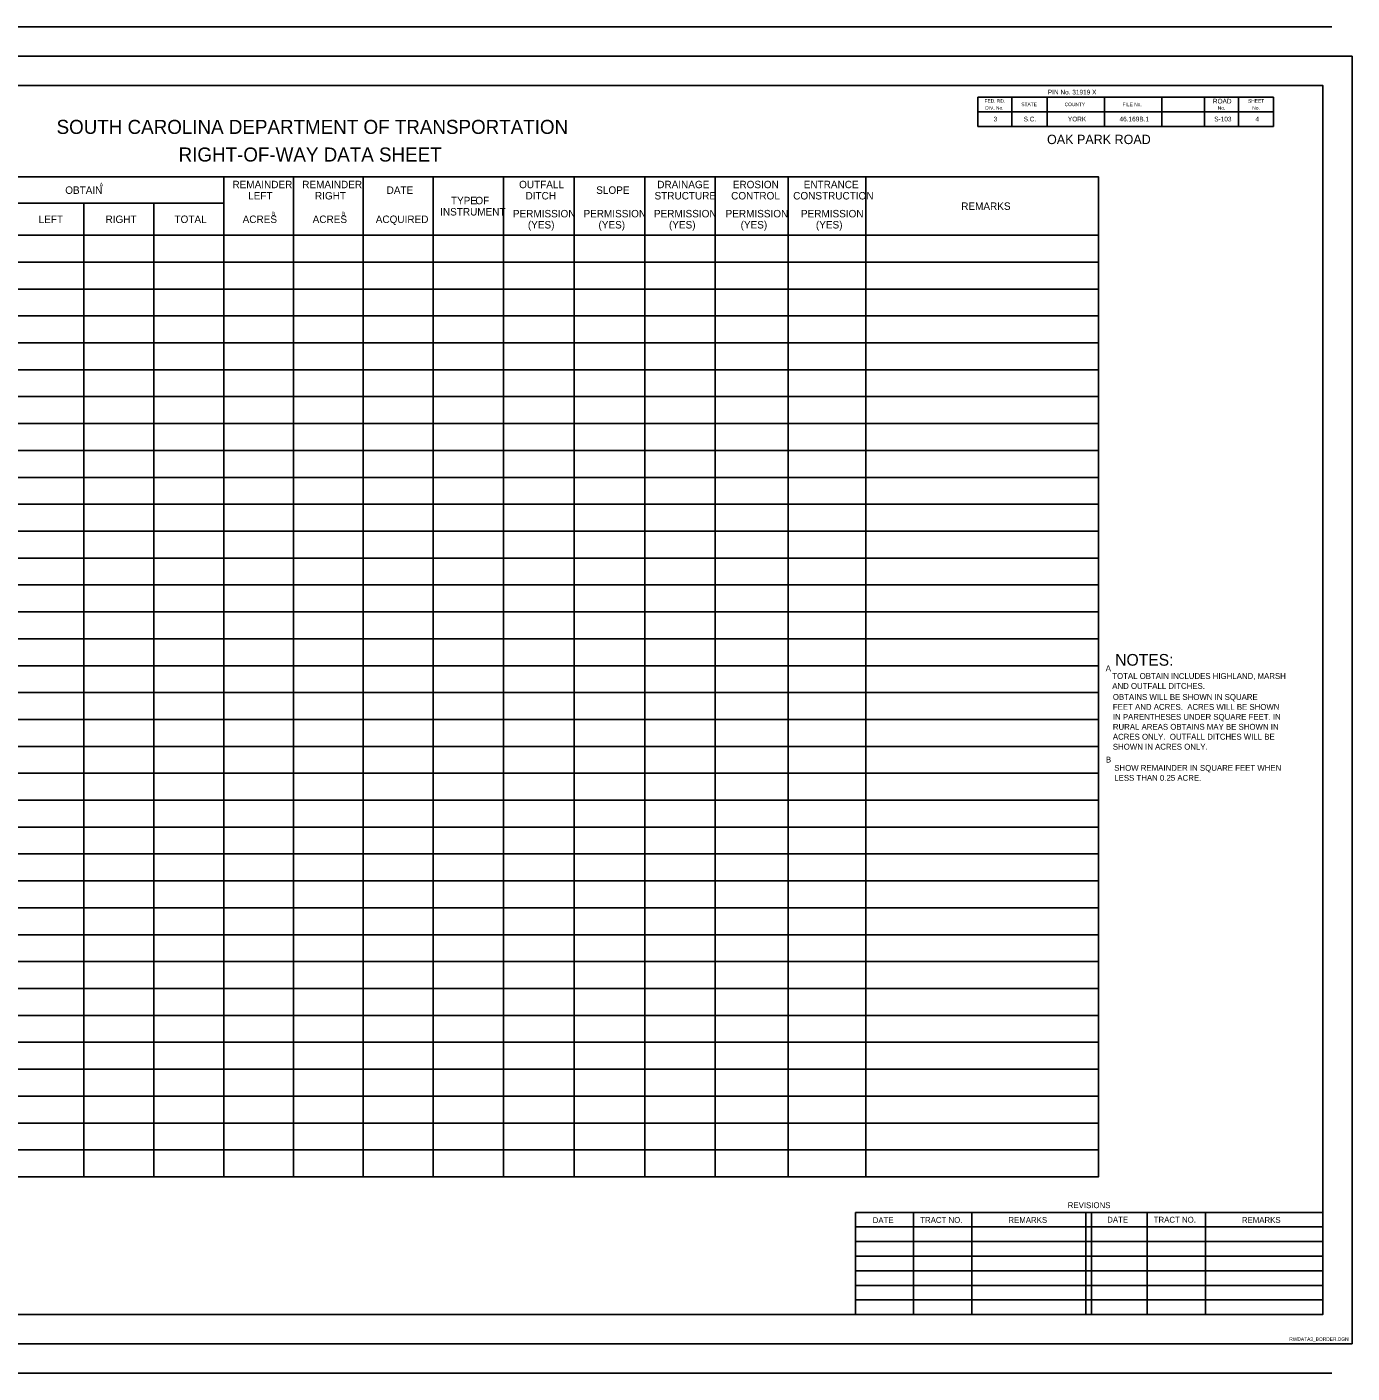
# Model space of a CAD drawing. Extents: x -19 to 1777, y -25 to 1125.
# Drawn here: x 646 to 1777, y -25 to 1125 of the extents above; entities that cross this region are included whole.
import ezdxf

# ---------------------------------------------------------------- set-up
doc = ezdxf.new("R2010")
doc.units = 0
for name, color, linetype in [('RD_SHT_Bndy', 7, 'Continuous'), ('RD_SHT_Iplotshp', 7, 'Continuous'), ('RD_SHT_MjGrid', 7, 'Continuous'), ('RD_SHT_TX', 7, 'Continuous'), ('RD_TX_RW', 7, 'Continuous')]:
    doc.layers.add(name, color=color, linetype=linetype)

msp = doc.modelspace()

# ---------------------------------------------------------------- linework, layer by layer
at = {"layer": 'RD_SHT_Bndy'}
for p, q in [((0, 1125), (1760, 1125)), ((0, 1100), (1760, 1100)), ((1457.9, 1065), (1710.4, 1065)), ((1457.9, 1065), (1457.9, 1052.5)), ((1486.9, 1065), (1486.9, 1052.5)), ((1516.9, 1065), (1516.9, 1052.5)), ((1565.9, 1065), (1565.9, 1052.5)), ((1614.9, 1065), (1614.9, 1052.5)), ((1651.4, 1065), (1651.4, 1052.5)), ((1680.4, 1065), (1680.4, 1052.5)), ((1710.4, 1065), (1710.4, 1052.5)), ((1457.9, 1052.5), (1710.4, 1052.5)), ((1457.9, 1052.5), (1457.9, 1040)), ((1486.9, 1052.5), (1486.9, 1049.4)), ((1486.9, 1049.4), (1486.9, 1040)), ((1516.9, 1052.5), (1516.9, 1040)), ((1565.9, 1052.5), (1565.9, 1040)), ((1614.9, 1052.5), (1614.9, 1040)), ((1651.4, 1052.5), (1651.4, 1040)), ((1680.4, 1052.5), (1680.4, 1040)), ((1710.4, 1052.5), (1710.4, 1040)), ((1457.9, 1040), (1710.4, 1040)), ((1353.4, 112.2), (1752.4, 112.2)), ((1353.4, 112.2), (1353.4, 25)), ((1402.9, 112.2), (1402.9, 25)), ((1452.7, 112.2), (1452.7, 25)), ((1549.9, 112.2), (1549.9, 25)), ((1554.9, 112.2), (1554.9, 25)), ((1602.3, 112.2), (1602.3, 25)), ((1652.1, 112.2), (1652.1, 25)), ((1353.4, 99.8), (1752.4, 99.8)), ((1353.4, 87.3), (1752.4, 87.3)), ((1353.4, 74.9), (1752.4, 74.9)), ((1353.4, 62.4), (1752.4, 62.4)), ((1353.4, 49.9), (1752.4, 49.9)), ((1353.4, 37.5), (1752.4, 37.5)), ((0, 0), (1760, 0)), ((0, -25), (1760, -25))]:
    msp.add_line(p, q, dxfattribs=at)
for points in [[(77.4, 1075), (1752.4, 1075), (1752.4, 25), (77.4, 25)], [(218, 142.7), (1560.9, 142.7), (1560.9, 996.8), (218, 996.8)]]:
    msp.add_lwpolyline(points, close=True, dxfattribs=at)
at = {"layer": 'RD_SHT_Iplotshp'}
msp.add_lwpolyline([(-18.6, 1100), (1777.4, 1100), (1777.4, 0), (-18.6, 0)], close=True, dxfattribs=at)
at = {"layer": 'RD_SHT_MjGrid'}
for p, q in [((218, 996.8), (1560.9, 996.8)), ((813.7, 142.7), (813.7, 996.8)), ((873.3, 142.7), (873.3, 996.8)), ((932.9, 142.7), (932.9, 996.8)), ((992.6, 142.7), (992.6, 996.8)), ((1052.8, 142.7), (1052.8, 996.8)), ((1113.1, 142.7), (1113.1, 996.8)), ((1173.3, 142.7), (1173.3, 996.8)), ((1233.6, 142.7), (1233.6, 996.8)), ((1295.7, 142.7), (1295.7, 996.8)), ((1362.1, 142.7), (1362.1, 996.8)), ((1560.9, 142.7), (1560.9, 996.8)), ((575.2, 974.4), (813.7, 974.4)), ((694.4, 142.7), (694.4, 974.4)), ((754, 142.7), (754, 974.4)), ((218, 947.1), (1560.9, 947.1)), ((992.6, 947.1), (1362.1, 947.1)), ((1362.1, 947.1), (1560.9, 947.1)), ((218, 924.1), (1560.9, 924.1)), ((218, 901.1), (1560.9, 901.1)), ((218, 878.1), (1560.9, 878.1)), ((218, 855.1), (1560.9, 855.1)), ((218, 832.1), (1560.9, 832.1)), ((218, 809.2), (1560.9, 809.2)), ((218, 786.2), (1560.9, 786.2)), ((218, 763.2), (1560.9, 763.2)), ((218, 740.2), (1560.9, 740.2)), ((218, 717.2), (1560.9, 717.2)), ((218, 694.3), (1560.9, 694.3)), ((218, 671.3), (1560.9, 671.3)), ((218, 648.3), (1560.9, 648.3)), ((218, 625.3), (1560.9, 625.3)), ((218, 602.3), (1560.9, 602.3)), ((218, 579.3), (1560.9, 579.3)), ((218, 556.4), (1560.9, 556.4)), ((218, 533.4), (1560.9, 533.4)), ((218, 510.4), (1560.9, 510.4)), ((218, 487.4), (1560.9, 487.4)), ((218, 464.4), (1560.9, 464.4)), ((218, 441.4), (1560.9, 441.4)), ((218, 418.5), (1560.9, 418.5)), ((218, 395.5), (1560.9, 395.5)), ((218, 372.5), (1560.9, 372.5)), ((218, 349.5), (1560.9, 349.5)), ((218, 326.5), (1560.9, 326.5)), ((218, 303.6), (1560.9, 303.6)), ((218, 280.6), (1560.9, 280.6)), ((218, 257.6), (1560.9, 257.6)), ((218, 234.6), (1560.9, 234.6)), ((218, 211.6), (1560.9, 211.6)), ((218, 188.6), (1560.9, 188.6)), ((218, 165.7), (1560.9, 165.7)), ((218, 142.7), (1560.9, 142.7))]:
    msp.add_line(p, q, dxfattribs=at)

# ---------------------------------------------------------------- texts
at = {"layer": 'RD_SHT_TX'}
for s, height, p in [('PIN No. 31919 X   ', 4, (1517.6, 1067.3)), ('FED. RD.', 3, (1463.5, 1060.3)), ('STATE', 3, (1494.9, 1057.3)), ('COUNTY', 3, (1531.9, 1057.3)), ('FILE No.', 3, (1581.4, 1057.3)), ('      ROAD      ', 4, (1649.3, 1059.6)), ('SHEET', 3, (1688.5, 1060.3)), ('DIV. No.', 3, (1464.1, 1054.3)), ('3', 4, (1471.2, 1044.3)), ('S.C.', 4, (1496.9, 1044.3)), ('      YORK      ', 4, (1525.5, 1044.3)), ('   46.169B.1    ', 4, (1574.2, 1044.3)), ('     S-103      ', 4, (1652, 1044.3)), ('No.', 3, (1662.7, 1054.3)), ('No.', 3, (1692.2, 1054.3)), ('       4        ', 4, (1684.1, 1044.3)), ('SOUTH CAROLINA DEPARTMENT OF TRANSPORTATION', 12, (671, 1033.6)), ('OAK PARK ROAD                  ', 8, (1516.9, 1024.9)), ('RIGHT-OF-WAY DATA SHEET', 12, (775.2, 1010)), ('NOTES:', 10, (1575.1, 579.3)), ('A', 5, (1567, 574.6)), ('AND OUTFALL DITCHES. ', 5, (1572.6, 559.5)), ('TOTAL OBTAIN INCLUDES HIGHLAND, MARSH', 5, (1572.6, 568)), ('OBTAINS WILL BE SHOWN IN SQUARE', 5, (1573.1, 550.1)), ('FEET AND ACRES.  ACRES WILL BE SHOWN ', 5, (1573.1, 541.6)), ('IN PARENTHESES UNDER SQUARE FEET. IN ', 5, (1573.1, 533.1)), ('RURAL AREAS OBTAINS MAY BE SHOWN IN', 5, (1573.1, 524.6)), ('ACRES ONLY.  OUTFALL DITCHES WILL BE', 5, (1573.1, 516.1)), ('SHOWN IN ACRES ONLY.', 5, (1573.1, 507.6)), ('B', 5, (1567.2, 496.6)), ('SHOW REMAINDER IN SQUARE FEET WHEN ', 5, (1574.3, 489.5)), ('LESS THAN 0.25 ACRE.', 5, (1574.3, 481)), ('REVISIONS', 5, (1534.6, 115.9)), ('DATE', 5, (1368, 103.1)), ('TRACT NO.', 5, (1408.6, 103.3)), ('REMARKS', 5, (1483.9, 103.3)), ('DATE', 5, (1568.3, 103.5)), ('TRACT NO.', 5, (1608, 103.5)), ('REMARKS', 5, (1683.3, 103.3)), ('RWDATA3_BORDER.DGN', 3, (1723.8, 2.5))]:
    msp.add_text(s, height=height, dxfattribs=at).set_placement(p)
at = {"layer": 'RD_TX_RW'}
for s, height, p in [('A', 3.19, (707.8, 988.8)), ('REMAINDER', 6.37, (821.2, 987.2)), ('REMAINDER', 6.37, (880.8, 987.2)), ('OUTFALL', 6.37, (1066, 987.2)), ('DRAINAGE', 6.37, (1184, 987.2)), ('EROSION', 6.37, (1248.5, 987.2)), ('ENTRANCE', 6.37, (1309.1, 987.2)), ('OBTAIN', 6.37, (678.4, 982.4)), ('LEFT', 6.37, (834.6, 977.6)), ('RIGHT', 6.37, (891.7, 977.6)), ('DATE', 6.37, (952.9, 982.4)), ('TYPE', 6.37, (1007.8, 973.5)), (' OF', 6.37, (1026.3, 973.5)), ('DITCH', 6.37, (1071.5, 977.6)), ('SLOPE', 6.37, (1131.9, 982.4)), ('STRUCTURE', 6.37, (1181.7, 977.6)), ('CONTROL', 6.37, (1247.1, 977.6)), ('CONSTRUCTION', 6.371, (1300.1, 977.6)), ('B', 3.19, (854.8, 963.9)), (' B', 3.19, (913.4, 963.9)), ('INSTRUMENT', 6.37, (998.6, 963.9)), ('PERMISSION', 6.37, (1060.7, 962.3)), ('PERMISSION', 6.37, (1121, 962.3)), ('PERMISSION', 6.37, (1181.2, 962.3)), ('PERMISSION', 6.37, (1242.4, 962.3)), ('PERMISSION', 6.37, (1306.7, 962.3)), ('REMARKS', 6.37, (1443.6, 968.7)), ('LEFT', 6.37, (655.7, 957.5)), ('RIGHT', 6.37, (712.8, 957.5)), ('TOTAL', 6.37, (771.7, 957.5)), ('ACRES', 6.37, (829.9, 957.5)), ('ACRES', 6.37, (889.7, 957.5)), ('ACQUIRED', 6.37, (943.6, 957.5)), ('(YES)', 6.37, (1073.5, 952.8)), ('(YES)', 6.37, (1133.8, 952.8)), ('(YES)', 6.37, (1194, 952.8)), ('(YES)', 6.37, (1255.2, 952.8)), ('(YES)', 6.37, (1319.5, 952.8))]:
    msp.add_text(s, height=height, dxfattribs=at).set_placement(p)

doc.saveas('drawing.dxf')
